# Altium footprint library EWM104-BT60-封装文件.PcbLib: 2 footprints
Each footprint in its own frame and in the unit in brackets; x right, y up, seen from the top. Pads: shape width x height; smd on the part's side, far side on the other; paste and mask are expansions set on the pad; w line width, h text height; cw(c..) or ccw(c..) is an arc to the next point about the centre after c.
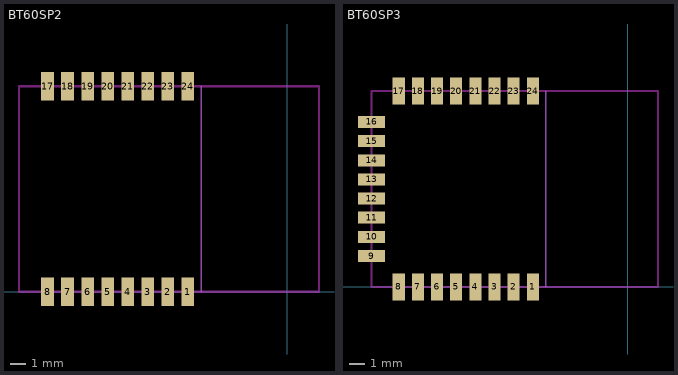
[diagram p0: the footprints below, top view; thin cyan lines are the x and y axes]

## BT60SP2 [mm]
pads (16):
  rect 0.8x1.8 smd paste+0 mask+0: 1(-6.295,0) 2(-7.565,0) 3(-8.835,0) 4(-10.105,0) 5(-11.375,0) 6(-12.645,0) 7(-13.915,0) 8(-15.185,0) 17(-15.185,13) 18(-13.915,13) 19(-12.645,13) 20(-11.375,13) 21(-10.105,13) 22(-8.835,13) 23(-7.565,13) 24(-6.295,13)
Keep-Out Layer:
  lines w0.15: -16.99,0 -16.99,13 ; -16.99,0 -16.99,13 ; -16.99,0 2.01,0 ; -16.99,0 2.01,0 ; -16.99,13 2.01,13 ; -16.99,13 2.01,13 ; 2.01,0 2.01,13 ; 2.01,0 2.01,13
Mechanical 7:
  lines w0.1: -5.451,0 -5.451,13

## BT60SP3 [mm]
pads (24):
  rect 0.8x1.8 smd paste+0 mask+0: 1(-6.295,0) 2(-7.565,0) 3(-8.835,0) 4(-10.105,0) 5(-11.375,0) 6(-12.645,0) 7(-13.915,0) 8(-15.185,0) 17(-15.185,13) 18(-13.915,13) 19(-12.645,13) 20(-11.375,13) 21(-10.105,13) 22(-8.835,13) 23(-7.565,13) 24(-6.295,13)
  rect 1.8x0.8 smd paste+0 mask+0: 9(-16.99,2.055) 10(-16.99,3.325) 11(-16.99,4.595) 12(-16.99,5.865) 13(-16.99,7.135) 14(-16.99,8.405) 15(-16.99,9.675) 16(-16.99,10.945)
Keep-Out Layer:
  lines w0.15: -16.99,0 -16.99,13 ; -16.99,0 -16.99,13 ; -16.99,0 2.01,0 ; -16.99,0 2.01,0 ; -16.99,13 2.01,13 ; -16.99,13 2.01,13 ; 2.01,0 2.01,13 ; 2.01,0 2.01,13
Mechanical 7:
  lines w0.1: -5.451,0 -5.451,13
